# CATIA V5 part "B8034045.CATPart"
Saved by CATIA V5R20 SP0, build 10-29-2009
Part number: B8034045
Revision: 4
Definition: design
Nomenclature: B8034045
Source: made
Description: NOT SPECIFIED
Bounding box of the stored display mesh (mm): x -30 to 30, y -30 to 30, z 0 to 45
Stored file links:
  C:\Users\Utente\Desktop\3D files B803\B8034045.CATPart
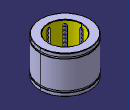
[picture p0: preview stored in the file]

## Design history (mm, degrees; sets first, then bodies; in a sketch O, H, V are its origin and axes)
Body1 "MANIFOLD_SOLID_BREP #38" (main body)
  Solid1: solid without history
Body2 "MANIFOLD_SOLID_BREP #76"
  Solid2: solid without history
Body3 "MANIFOLD_SOLID_BREP #114"
  Solid3: solid without history
Body4 "MANIFOLD_SOLID_BREP #152"
  Solid4: solid without history
Body5 "MANIFOLD_SOLID_BREP #190"
  Solid5: solid without history
Body6 "MANIFOLD_SOLID_BREP #228"
  Solid6: solid without history
Body7 "MANIFOLD_SOLID_BREP #266"
  Solid7: solid without history
Body8 "MANIFOLD_SOLID_BREP #304"
  Solid8: solid without history
Body9 "MANIFOLD_SOLID_BREP #2444"
  Solid9: solid without history
Body10 "MANIFOLD_SOLID_BREP #2482"
  Solid10: solid without history
Body11 "MANIFOLD_SOLID_BREP #2520"
  Solid11: solid without history
Body12 "MANIFOLD_SOLID_BREP #2558"
  Solid12: solid without history
Body13 "MANIFOLD_SOLID_BREP #2596"
  Solid13: solid without history
Body14 "MANIFOLD_SOLID_BREP #2634"
  Solid14: solid without history
Body15 "MANIFOLD_SOLID_BREP #2672"
  Solid15: solid without history
Body16 "MANIFOLD_SOLID_BREP #2710"
  Solid16: solid without history
Body17 "MANIFOLD_SOLID_BREP #2748"
  Solid17: solid without history
Body18 "MANIFOLD_SOLID_BREP #2786"
  Solid18: solid without history
Body19 "MANIFOLD_SOLID_BREP #2824"
  Solid19: solid without history
Body20 "MANIFOLD_SOLID_BREP #2862"
  Solid20: solid without history
Body21 "MANIFOLD_SOLID_BREP #2900"
  Solid21: solid without history
Body22 "MANIFOLD_SOLID_BREP #2938"
  Solid22: solid without history
Body23 "MANIFOLD_SOLID_BREP #2976"
  Solid23: solid without history
Body24 "MANIFOLD_SOLID_BREP #3014"
  Solid24: solid without history
Body25 "MANIFOLD_SOLID_BREP #3052"
  Solid25: solid without history
Body26 "MANIFOLD_SOLID_BREP #3090"
  Solid26: solid without history
Body27 "MANIFOLD_SOLID_BREP #3128"
  Solid27: solid without history
Body28 "MANIFOLD_SOLID_BREP #3166"
  Solid28: solid without history
Body29 "MANIFOLD_SOLID_BREP #3204"
  Solid29: solid without history
Body30 "MANIFOLD_SOLID_BREP #3242"
  Solid30: solid without history
Body31 "MANIFOLD_SOLID_BREP #3280"
  Solid31: solid without history
Body32 "MANIFOLD_SOLID_BREP #3318"
  Solid32: solid without history
Body33 "MANIFOLD_SOLID_BREP #3356"
  Solid33: solid without history
Body34 "MANIFOLD_SOLID_BREP #3394"
  Solid34: solid without history
Body35 "MANIFOLD_SOLID_BREP #3432"
  Solid35: solid without history
Body36 "MANIFOLD_SOLID_BREP #3470"
  Solid36: solid without history
Body37 "MANIFOLD_SOLID_BREP #3508"
  Solid37: solid without history
Body38 "MANIFOLD_SOLID_BREP #3546"
  Solid38: solid without history
Body39 "MANIFOLD_SOLID_BREP #3584"
  Solid39: solid without history
Body40 "MANIFOLD_SOLID_BREP #3622"
  Solid40: solid without history
Body41 "MANIFOLD_SOLID_BREP #3660"
  Solid41: solid without history
Body42 "MANIFOLD_SOLID_BREP #3698"
  Solid42: solid without history
Body43 "MANIFOLD_SOLID_BREP #3736"
  Solid43: solid without history
Body44 "MANIFOLD_SOLID_BREP #3774"
  Solid44: solid without history
Body45 "MANIFOLD_SOLID_BREP #3812"
  Solid45: solid without history
Body46 "MANIFOLD_SOLID_BREP #3850"
  Solid46: solid without history
Body47 "MANIFOLD_SOLID_BREP #3888"
  Solid47: solid without history
Body48 "MANIFOLD_SOLID_BREP #3926"
  Solid48: solid without history
Body49 "MANIFOLD_SOLID_BREP #3964"
  Solid49: solid without history
Body50 "MANIFOLD_SOLID_BREP #4002"
  Solid50: solid without history
Body51 "MANIFOLD_SOLID_BREP #4040"
  Solid51: solid without history
Body52 "MANIFOLD_SOLID_BREP #4078"
  Solid52: solid without history
Body53 "MANIFOLD_SOLID_BREP #4116"
  Solid53: solid without history
Body54 "MANIFOLD_SOLID_BREP #4154"
  Solid54: solid without history
Body55 "MANIFOLD_SOLID_BREP #4192"
  Solid55: solid without history
Body56 "MANIFOLD_SOLID_BREP #4230"
  Solid56: solid without history
Body57 "MANIFOLD_SOLID_BREP #4268"
  Solid57: solid without history
Body58 "MANIFOLD_SOLID_BREP #4306"
  Solid58: solid without history
Body59 "MANIFOLD_SOLID_BREP #4344"
  Solid59: solid without history
Body60 "MANIFOLD_SOLID_BREP #4382"
  Solid60: solid without history
Body61 "MANIFOLD_SOLID_BREP #4420"
  Solid61: solid without history
Body62 "MANIFOLD_SOLID_BREP #4458"
  Solid62: solid without history
Body63 "MANIFOLD_SOLID_BREP #4496"
  Solid63: solid without history
Body64 "MANIFOLD_SOLID_BREP #4534"
  Solid64: solid without history
Body65 "MANIFOLD_SOLID_BREP #4572"
  Solid65: solid without history
Body66 "MANIFOLD_SOLID_BREP #4610"
  Solid66: solid without history
Body67 "MANIFOLD_SOLID_BREP #4648"
  Solid67: solid without history
Body68 "MANIFOLD_SOLID_BREP #4686"
  Solid68: solid without history
Body69 "MANIFOLD_SOLID_BREP #4724"
  Solid69: solid without history
Body70 "MANIFOLD_SOLID_BREP #4762"
  Solid70: solid without history
Body71 "MANIFOLD_SOLID_BREP #4800"
  Solid71: solid without history
Body72 "MANIFOLD_SOLID_BREP #4838"
  Solid72: solid without history
Body73 "MANIFOLD_SOLID_BREP #4876"
  Solid73: solid without history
